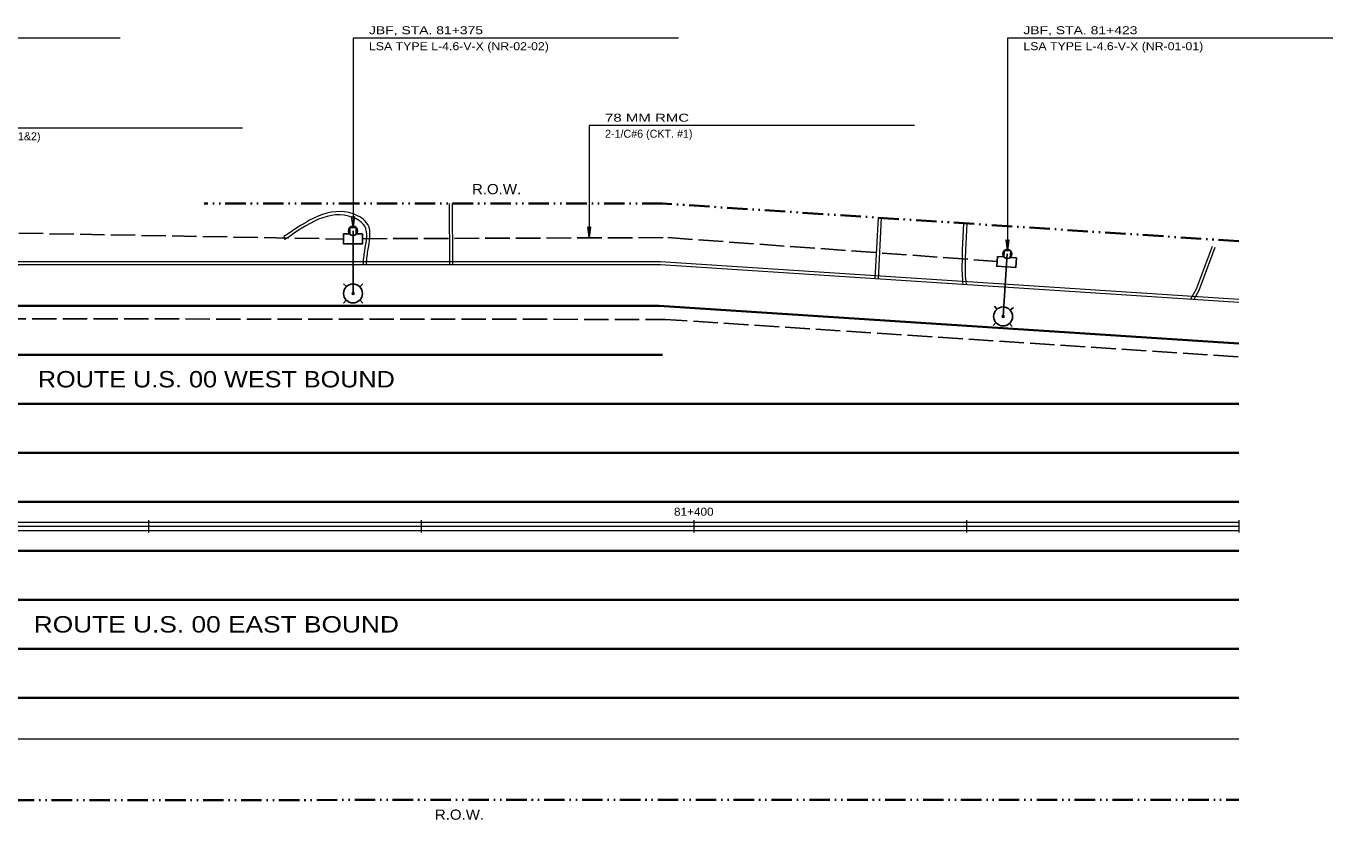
# Model space of a CAD drawing. Extents: x 168423 to 169398, y 223542 to 223937.
# Drawn here: x 168518.5 to 168614.3, y 223612.7 to 223671 of the extents above; entities that cross this region are included whole.
import ezdxf
from ezdxf.enums import TextEntityAlignment as Align

# ---------------------------------------------------------------- set-up
doc = ezdxf.new("R2010")
doc.units = 0
doc.header["$LTSCALE"] = 0.3
doc.header["$PDMODE"] = 32
doc.header["$PDSIZE"] = 0.15
doc.linetypes.add('DASH_DOUBLE_DOT', pattern=[9.2, 5, -1.2, 0.3, -1.2, 0.3, -1.2])
doc.linetypes.add('LONG_DASHED', pattern=[7.5, 6, -1.5])
for name, color, linetype, lineweight in [('1', 7, 'Continuous', 13), ('11', 7, 'Continuous', 13), ('29', 7, 'Continuous', 25), ('31', 7, 'Continuous', 25), ('36', 7, 'Continuous', 35), ('5', 7, 'Continuous', 25), ('7', 7, 'Continuous', 25)]:
    doc.layers.add(name, color=color, linetype=linetype, lineweight=lineweight)

msp = doc.modelspace()

# ---------------------------------------------------------------- linework, layer by layer
at = {"layer": '1', "linetype": 'DASH_DOUBLE_DOT', "lineweight": 35}
for p, q in [((168565.1597, 223657.9671), (168531.5216, 223657.9671)), ((168607.4519, 223655.1989), (168565.1597, 223657.9671)), ((168506.4362, 223614.1671), (168607.4519, 223614.1672))]:
    msp.add_line(p, q, dxfattribs=at)
at = {"layer": '1'}
for p, q in [((168549.5523, 223653.4673), (168549.524, 223657.9671)), ((168549.7823, 223653.4673), (168549.754, 223657.9671)), ((168580.9771, 223656.9318), (168580.7423, 223652.4377)), ((168581.2066, 223656.9168), (168580.9718, 223652.4227)), ((168587.1792, 223654.5521), (168587.2752, 223656.5195)), ((168587.409, 223654.5408), (168587.5048, 223656.5045)), ((168537.3783, 223655.5399), (168537.4497, 223655.3213)), ((168587.1641, 223653.9343), (168587.1792, 223654.5521)), ((168587.3941, 223653.9286), (168587.4092, 223654.5464)), ((168604.3331, 223651.6934), (168605.4986, 223654.8456)), ((168604.5421, 223651.5956), (168605.7143, 223654.7659)), ((168565.0197, 223653.6973), (168455.0122, 223653.6972)), ((168565.0122, 223653.4673), (168455.0122, 223653.4672)), ((168607.4519, 223650.6894), (168565.0122, 223653.4673)), ((168607.4519, 223650.9199), (168565.0197, 223653.6973)), ((168603.8911, 223650.9225), (168604.3331, 223651.6934)), ((168604.1466, 223650.9058), (168604.5421, 223651.5956)), ((168427.4519, 223634.5672), (168607.4519, 223634.5673)), ((168427.4519, 223634.2672), (168607.4519, 223634.2673)), ((168527.4519, 223634.7173), (168527.4519, 223633.8172)), ((168547.4519, 223634.7173), (168547.4518, 223633.8172)), ((168567.4518, 223634.7173), (168567.4519, 223633.8172)), ((168587.4519, 223634.7173), (168587.4519, 223633.8174)), ((168607.4519, 223634.7173), (168607.4519, 223633.8174)), ((168427.4519, 223633.9672), (168607.4519, 223633.9674)), ((168501.8189, 223618.6672), (168607.4519, 223618.6673))]:
    msp.add_line(p, q, dxfattribs=at)
for points in [[(168543.4261, 223653.4673), (168543.5399, 223654.493), (168543.5348, 223656.4299), (168542.473, 223657.2046), (168537.3783, 223655.5399)], [(168543.1978, 223653.495), (168543.3099, 223654.5054), (168543.3051, 223656.3128), (168542.4325, 223656.9494), (168537.4497, 223655.3213)], [(168587.2203, 223652.0137), (168587.1577, 223652.8722), (168587.1641, 223653.9343)], [(168587.449, 223652.04), (168587.3878, 223652.8799), (168587.3941, 223653.9329)]]:
    msp.add_spline(points, degree=3, dxfattribs=at)
at = {"layer": '11'}
for p, q in [((168525.3589, 223670.113), (168501.4854, 223670.113)), ((168542.4541, 223670.113), (168542.4542, 223656.2021)), ((168566.3276, 223670.113), (168542.4541, 223670.113)), ((168590.467, 223670.113), (168590.4672, 223654.5016)), ((168614.3405, 223670.113), (168590.467, 223670.113))]:
    msp.add_line(p, q, dxfattribs=at)
for points in [[(168534.3314, 223663.4984), (168510.4579, 223663.4984), (168510.453, 223655.931)], [(168583.6484, 223663.6877), (168559.7749, 223663.6877), (168559.775, 223655.4433)]]:
    msp.add_lwpolyline(points, dxfattribs=at)
for points in [[(168542.5536, 223657.0154), (168542.4542, 223656.2021), (168542.3458, 223657.0154), (168542.4542, 223656.934)], [(168559.8744, 223656.2566), (168559.775, 223655.4433), (168559.6666, 223656.2566), (168559.775, 223656.1752)], [(168590.5666, 223655.3149), (168590.4672, 223654.5016), (168590.3588, 223655.3149), (168590.4672, 223655.2335)]]:
    msp.add_lwpolyline(points, close=True, dxfattribs=at)
at = {"layer": '29'}
for centre in [(168542.4541, 223655.9672), (168590.4519, 223654.2672)]:
    msp.add_circle(centre, 0.3355, dxfattribs=at)
at = {"layer": '31'}
for p, q in [((168542.4541, 223655.9672), (168542.4541, 223651.3672)), ((168590.1513, 223649.677), (168590.4519, 223654.2672))]:
    msp.add_line(p, q, dxfattribs=at)
at = {"layer": '36'}
for p, q in [((168564.9157, 223650.4672), (168455.0124, 223650.4671)), ((168607.4519, 223647.683), (168564.9157, 223650.4672)), ((168427.4519, 223646.8671), (168565.1597, 223646.8672)), ((168427.4519, 223643.2671), (168607.4519, 223643.2672)), ((168427.4519, 223639.6671), (168607.4519, 223639.6672)), ((168427.4519, 223636.0671), (168607.4519, 223636.0672)), ((168427.4519, 223632.4671), (168607.4519, 223632.4673)), ((168427.4519, 223628.8671), (168607.4519, 223628.8673)), ((168427.4519, 223625.2671), (168607.4519, 223625.2673)), ((168427.4519, 223621.667), (168607.4519, 223621.6672))]:
    msp.add_line(p, q, dxfattribs=at)
at = {"layer": '5', "linetype": 'LONG_DASHED'}
for p, q in [((168502.1771, 223656.081), (168541.7447, 223655.364)), ((168607.388, 223646.706), (168565.3437, 223649.458))]:
    msp.add_line(p, q, dxfattribs=at)
at = {"layer": '5'}
for p, q in [((168542.6935, 223656.2021), (168542.6935, 223655.7323)), ((168541.7447, 223655.7323), (168542.2146, 223655.7323)), ((168542.6935, 223655.7323), (168543.1544, 223655.7323)), ((168590.7061, 223654.486), (168590.6754, 223654.0172)), ((168589.7287, 223654.0791), (168590.1976, 223654.0484)), ((168590.6754, 223654.0172), (168591.1354, 223653.9871))]:
    msp.add_line(p, q, dxfattribs=at)
at = {"layer": '5', "linetype": 'LONG_DASHED'}
for points in [[(168442.2465, 223657.8078), (168451.4028, 223649.563), (168565.3437, 223649.458)], [(168543.1544, 223655.3841), (168565.5584, 223655.4639), (168589.7054, 223653.723)]]:
    msp.add_lwpolyline(points, dxfattribs=at)
at = {"layer": '5'}
for points in [[(168542.2146, 223655.7323), (168542.2146, 223656.2021), (168542.6935, 223656.2021)], [(168543.1544, 223655.7323), (168543.1544, 223655.0184), (168541.7447, 223655.0184), (168541.7447, 223655.7323)], [(168590.1976, 223654.0484), (168590.2283, 223654.5172), (168590.7061, 223654.486)], [(168591.1354, 223653.9871), (168591.0887, 223653.2747), (168589.682, 223653.3668), (168589.7287, 223654.0791)]]:
    msp.add_lwpolyline(points, dxfattribs=at)
at = {"layer": '7'}
for p, q in [((168541.7583, 223652.072), (168541.9661, 223651.8732)), ((168543.168, 223652.0811), (168542.9421, 223651.8552)), ((168541.9571, 223650.8702), (168541.7583, 223650.6624)), ((168542.9511, 223650.8883), (168543.168, 223650.6624)), ((168589.503, 223650.4258), (168589.6974, 223650.2138)), ((168590.9103, 223650.3427), (168590.6701, 223650.1321)), ((168589.6229, 223649.2135), (168589.4109, 223649.0192)), ((168590.6159, 223649.1667), (168590.8176, 223648.9271))]:
    msp.add_line(p, q, dxfattribs=at)
for centre in [(168542.4496, 223651.3672), (168590.1468, 223649.6773)]:
    msp.add_circle(centre, 0.6965, dxfattribs=at)
for p in [(168542.4541, 223651.3672), (168590.1513, 223649.677)]:
    msp.add_point(p, dxfattribs=at)

# ---------------------------------------------------------------- texts
at = {"layer": '1'}
for s, height, width, p in [('R.O.W.', 0.7499, 1.1, (168552.983, 223658.6536)), ('ROUTE U.S. 00 WEST BOUND', 1.202, 1.15, (168532.4221, 223644.4663)), ('81+400', 0.5873, 1.1, (168567.4515, 223635.0442)), ('ROUTE U.S. 00 EAST BOUND', 1.202, 1.2, (168532.4221, 223626.4663)), ('R.O.W.', 0.7499, 1.1, (168550.2624, 223612.7172))]:
    msp.add_text(s, height=height, dxfattribs=dict(at, width=width)).set_placement(p, align=Align.CENTER)
at = {"layer": '11'}
for s, width, p in [('JBF, STA. 81+375                     ', 1.3, (168543.6198, 223670.4022)), ('JBF, STA. 81+423               ', 1.3, (168591.6327, 223670.4022)), ('LSA TYPE L-4.6-V-X (NR-02-02)          ', 1.15, (168543.6198, 223669.2275)), ('LSA TYPE L-4.6-V-X (NR-01-01)          ', 1.15, (168591.6327, 223669.2275)), ('78 MM RMC                            ', 1.4, (168560.9406, 223663.9769))]:
    msp.add_text(s, height=0.5873, dxfattribs=dict(at, width=width)).set_placement(p)
for s, p in [('4-1/C#6 (CKTS. #1&2)                   ', (168511.6236, 223662.6129)), ('2-1/C#6 (CKT. #1)                 ', (168560.9406, 223662.8022))]:
    msp.add_text(s, height=0.5873, dxfattribs=at).set_placement(p)

doc.saveas('drawing.dxf')
